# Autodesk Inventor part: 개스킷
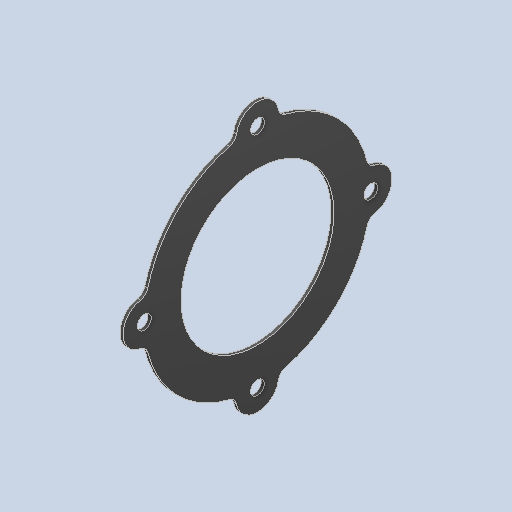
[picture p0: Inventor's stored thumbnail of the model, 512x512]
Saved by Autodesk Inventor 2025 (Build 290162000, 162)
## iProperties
Created: 2025-08
Part Number: 개스킷
Material: 황동, 연질 노란색
Document SubType Name: Modeling
Designer: infra02
Density: 8.47 g/cm^3
Appearance: 기본값
Author: jhkim
Sending System: Autodesk Inventor 2026
Preprocessor: ST-DEVELOPER v20.1
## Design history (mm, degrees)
feature "솔리드2"
node "솔리드1"
